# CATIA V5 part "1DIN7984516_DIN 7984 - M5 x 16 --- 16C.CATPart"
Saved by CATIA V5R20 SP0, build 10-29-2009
Part number: 1DIN7984516_DIN 7984 - M5 x 16 --- 16C
Revision: ANY
Definition: UNKNOWN
Nomenclature: 1DIN7984516_DIN 7984 - M5 x 16 --- 16C
Source: Unknown
Bounding box of the stored display mesh (mm): x 0 to 19.5, y -4.25 to 4.25, z -4.25 to 4.25
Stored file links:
  C:\Users\Utente\Desktop\IO LAVORO\3D X SITO CF\CUMSA\3D files PW\pw080825\pw080825_ejection\1DIN7984516_DIN 7984 - M5 x 16 --- 16C.CATPart
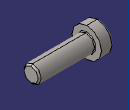
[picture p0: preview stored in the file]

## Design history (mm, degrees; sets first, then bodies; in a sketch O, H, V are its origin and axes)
Body1 "Hex" (main body)
  Solid1: solid without history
